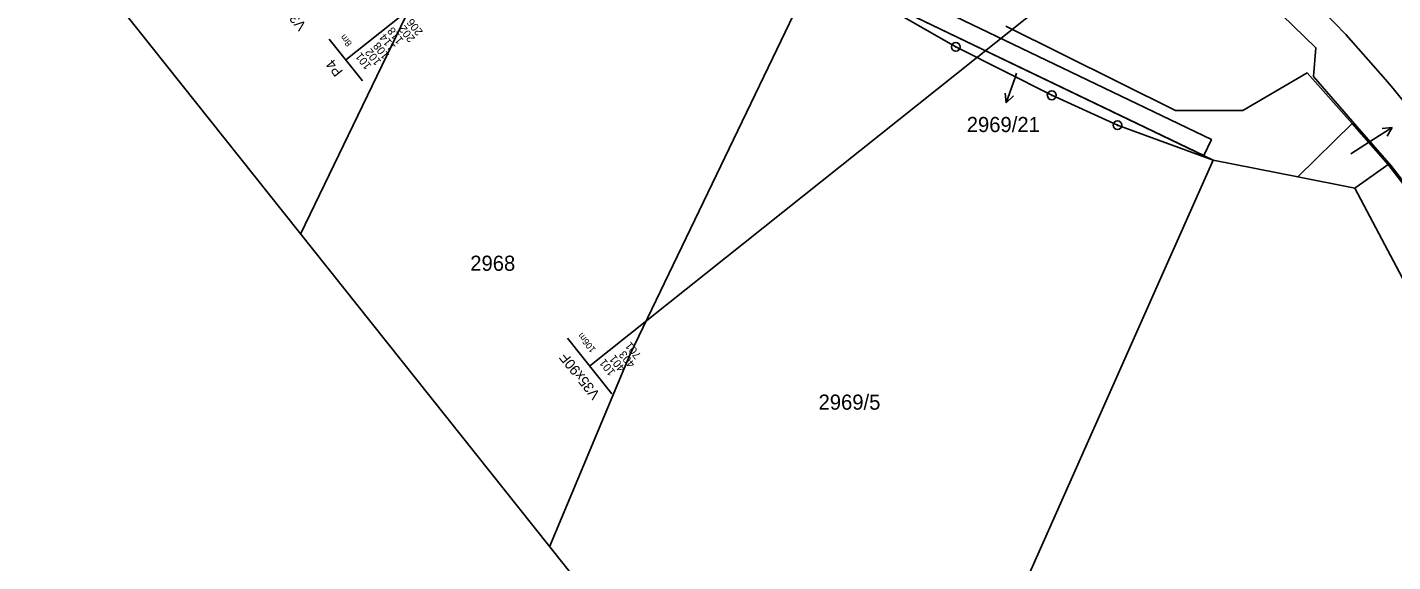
# Model space of a CAD drawing. Extents: x -620412 to -620034, y -1122986 to -1122565.
# Drawn here: x -620334.9 to -620181.4, y -1122830 to -1122770 of the extents above; entities that cross this region are included whole.
import ezdxf

# ---------------------------------------------------------------- set-up
doc = ezdxf.new("R2010")
doc.units = 0
for name, color, linetype in [('HranDP', 7, 'Continuous'), ('Hranice parcel', 7, 'Continuous'), ('Parcelní čísla', 7, 'Continuous'), ('Pop  PČ popisy', 7, 'Continuous'), ('Rámečky-tisk', 7, 'Continuous'), ('Vnitřní kresba', 7, 'Continuous'), ('Vrstva 1', 7, 'Continuous'), ('Vrstva 33', 7, 'Continuous'), ('Věcná břemena k části', 7, 'Continuous'), ('Značky bodu BP', 7, 'Continuous')]:
    doc.layers.add(name, color=color, linetype=linetype)

msp = doc.modelspace()

# ---------------------------------------------------------------- linework, layer by layer
at = {"layer": 'HranDP'}
msp.add_line((-620185.98, -1122780.81), (-620181.92, -1122785.4), dxfattribs=at)
for points in [[(-620224.92, -1122769.84), (-620205.84, -1122779.33), (-620198.25, -1122779.35), (-620191.03, -1122775.11), (-620185.98, -1122780.81)], [(-620152.84, -1122837.4), (-620159.98, -1122819.68), (-620173.68, -1122796.12), (-620181.92, -1122785.4)]]:
    msp.add_lwpolyline(points, dxfattribs=at)
at = {"layer": 'Hranice parcel'}
for p, q in [((-620284.57, -1122752.56), (-620304.19, -1122793.24)), ((-620201.6, -1122784.9), (-620243.2, -1122764.91)), ((-620192.09, -1122786.79), (-620185.98, -1122780.81)), ((-620185.98, -1122780.81), (-620181.92, -1122785.4)), ((-620192.09, -1122786.79), (-620201.6, -1122784.9))]:
    msp.add_line(p, q, dxfattribs=at)
for points in [[(-620276.2, -1122828.36), (-620267.15, -1122806.71), (-620246.32, -1122763.41)], [(-620201.6, -1122784.9), (-620212.35, -1122780.98), (-620219.74, -1122777.62), (-620230.53, -1122772.18), (-620243.2, -1122764.91)], [(-620224.92, -1122769.84), (-620205.84, -1122779.33), (-620198.25, -1122779.35), (-620191.03, -1122775.11), (-620185.98, -1122780.81)], [(-620234.78, -1122859.86), (-620228.39, -1122845.14), (-620201.6, -1122784.9)], [(-620181.92, -1122785.4), (-620185.65, -1122788.07), (-620192.09, -1122786.79)], [(-620152.84, -1122837.4), (-620159.98, -1122819.68), (-620173.68, -1122796.12), (-620181.92, -1122785.4)]]:
    msp.add_lwpolyline(points, dxfattribs=at)
at = {"layer": 'Pop  PČ popisy'}
for p, q in [((-620223.87, -1122775.64), (-620224.85, -1122778.48)), ((-620223.7, -1122775.15), (-620223.87, -1122775.64)), ((-620224.85, -1122778.48), (-620224.99, -1122777.37)), ((-620224.85, -1122778.48), (-620224.05, -1122777.69)), ((-620184.01, -1122782.84), (-620181.46, -1122781.25)), ((-620181.46, -1122781.25), (-620182.58, -1122781.36)), ((-620181.46, -1122781.25), (-620182.05, -1122782.21)), ((-620186.13, -1122784.19), (-620184.01, -1122782.84))]:
    msp.add_line(p, q, dxfattribs=at)
at = {"layer": 'Rámečky-tisk'}
msp.add_lwpolyline([(-620412.11, -1122657.76), (-620150.41, -1122986.26), (-620034.26, -1122893.74), (-620295.96, -1122565.23)], dxfattribs=at)
at = {"layer": 'Vnitřní kresba'}
msp.add_line((-620185.65, -1122788.07), (-620157.72, -1122840.99), dxfattribs=at)
at = {"layer": 'Vrstva 1'}
for points in [[(-620173.84, -1122795.49), (-620176.67, -1122791.87), (-620181.59, -1122785.57), (-620185.43, -1122781.13), (-620190.33, -1122775.52), (-620190.05, -1122772.28), (-620198.93, -1122763.63), (-620211.63, -1122752.65), (-620228.5, -1122738.51), (-620248.32, -1122722.77)], [(-620191.91, -1122765.36), (-620186.69, -1122770.81), (-620182.21, -1122775.85), (-620181.54, -1122776.64), (-620176.09, -1122783.33)]]:
    msp.add_lwpolyline(points, dxfattribs=at)
at = {"layer": 'Vrstva 33'}
for p, q in [((-620247.56, -1122732.58), (-620299.12, -1122773.65)), ((-620207.08, -1122756.59), (-620271.7, -1122808.06)), ((-620300.99, -1122771.3), (-620297.25, -1122776)), ((-620274.19, -1122804.94), (-620269.21, -1122811.19))]:
    msp.add_line(p, q, dxfattribs=at)
at = {"layer": 'Věcná břemena k části'}
msp.add_lwpolyline([(-620409.99, -1122656.07), (-620389.78, -1122673.21), (-620362.07, -1122697.07), (-620350.79, -1122712.11), (-620329.91, -1122699.79), (-620318.75, -1122707.75), (-620310.23, -1122716.49), (-620285.9, -1122736.09), (-620287.87, -1122738.92), (-620280.66, -1122744.45), (-620246.32, -1122763.41), (-620202.66, -1122784.39), (-620201.79, -1122782.59), (-620245.45, -1122761.61), (-620279.7, -1122742.7), (-620285.15, -1122738.52), (-620283.23, -1122735.73), (-620308.89, -1122715.01), (-620317.45, -1122706.23), (-620329.81, -1122697.41), (-620350.27, -1122709.47), (-620360.61, -1122695.69), (-620388.48, -1122671.69), (-620408.4, -1122654.8)], dxfattribs=at)
at = {"layer": 'Značky bodu BP'}
for centre, radius in [((-620230.53, -1122772.18), 0.5), ((-620230.53, -1122772.18), 0.0303), ((-620219.74, -1122777.62), 0.5), ((-620219.74, -1122777.62), 0.0303), ((-620212.35, -1122780.98), 0.5), ((-620212.35, -1122780.98), 0.0303)]:
    msp.add_circle(centre, radius, dxfattribs=at)

# ---------------------------------------------------------------- texts
at = {"layer": 'Parcelní čísla'}
for s, p in [('2969/21', (-620229.3, -1122781.76)), ('2968', (-620285.12, -1122797.35)), ('2969/5', (-620245.96, -1122812.96))]:
    msp.add_text(s, height=1.7, dxfattribs=at).set_placement(p)
at = {"layer": 'Vrstva 33'}
for s, height, p in [('V35x90F', 1.15, (-620303.48, -1122769.78)), ('118', 0.9, (-620292.57, -1122771.44)), ('202', 0.9, (-620291.27, -1122771.23)), ('206', 0.9, (-620290.39, -1122770.48)), ('8m', 0.75, (-620298.37, -1122771.78)), ('108', 0.9, (-620294.17, -1122773.12)), ('114', 0.9, (-620293.45, -1122772.18)), ('101', 0.9, (-620296.17, -1122774.3)), ('102', 0.9, (-620295.07, -1122773.84)), ('P4', 1.15, (-620299.37, -1122774.94)), ('106m', 0.75, (-620270.96, -1122806.19)), ('701', 0.9, (-620265.85, -1122806.82)), ('V35x90F', 1.15, (-620270.46, -1122811.23)), ('101', 0.9, (-620268.75, -1122808.72)), ('401', 0.9, (-620267.63, -1122808.28)), ('403', 0.9, (-620266.53, -1122807.82))]:
    msp.add_text(s, height=height, rotation=128.542, dxfattribs=at).set_placement(p)

doc.saveas('drawing.dxf')
